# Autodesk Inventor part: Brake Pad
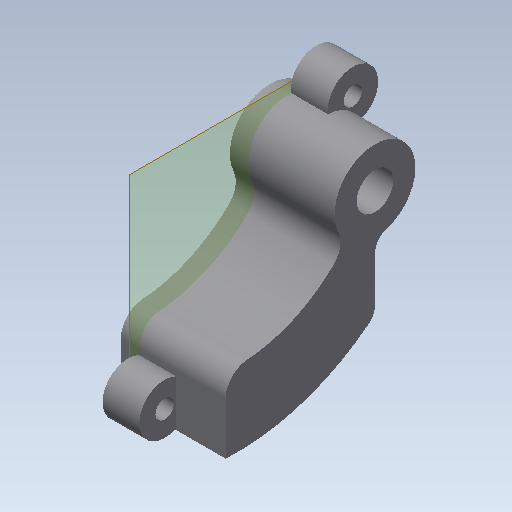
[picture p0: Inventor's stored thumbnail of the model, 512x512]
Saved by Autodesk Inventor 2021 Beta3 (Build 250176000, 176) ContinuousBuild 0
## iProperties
Created: 2012-08
Part Number: Brake Pad
Material: Generic
Document SubType Name: Modeling
Designer: John
Density: 1 g/cm^3
Appearance: Default
Author: John
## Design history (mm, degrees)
sketch "Sketch1"
  geometry: L1 (7.62, -5.283)-(7.62, -8.958); L2 (-0.635, -11.743)-(-0.635, -7.593); A1 r 11.76 centre (0, 0) between (-0.635, -11.743) and (7.62, -8.958); A2 r 7.62 centre (0, 0) between (-0.635, -7.593) and (6.047, -4.636); A3 r 2.235 centre (7.62, -3.048) between (7.62, -5.283) and (6.047, -4.636); 1 further point
  constraints: 6 point on circle, 4 end point, 3 centre point, 2 coincident, 1 parallel, 1 vertical, 1 vertical alignment
  dimensions: "d0" = 11.7602 radius of A1; "d1" = 7.62 radius of A2; "d8" = 2.2352 radius of A3; "d9" = 7.62 horizontal distance of A3.centre A2.centre; "d10" = 3.048 vertical distance of A1.centre A3.centre; "d11" = 0.635 distance from line of point (0, 0) L2
extrude "Extrusion1" new body sketch "Sketch1" distance "d12" = 5.7912; taper "d13" = 0 deg
fillet "Fillet1" dims "d14" = 1.27
fillet "Fillet2" dims "d15" = 0.889
fillet "Fillet3" dims "d16" = 0.889
workplane "Work Plane1"
sketch "Sketch2"
  geometry: L1 (-7.593, -0.635)-(-11.743, -0.635) reference; L2 (-8.537, 7.62)-(-6.043, 7.62) reference; C1 r 1.397 at (-10.414, -1.27); C2 r 1.397 at (-0.635, 9.144); A1 r 1.27 centre (-4.534, 4.446) between (-3.996, 5.596) and (-5.441, 5.335) reference; A2 r 7.62 centre (0, 0) between (-5.441, 5.335) and (-7.593, -0.635) reference; A3 r 11.76 centre (0, 0) between (-9.235, 7.281) and (-11.743, -0.635) reference; A4 r 0.889 centre (-8.537, 6.731) between (-8.537, 7.62) and (-9.235, 7.281) reference; A5 r 0.889 centre (-6.043, 8.509) between (-6.043, 7.62) and (-5.191, 8.256) reference; A6 r 2.235 centre (-3.048, 7.62) between (-3.996, 5.596) and (-5.191, 8.256) reference; 1 further point
  constraints: 2 centre point
  dimensions: "d18" = 1.397 radius of C1; "d19" = 1.27 vertical distance of point (0, 0) C1.centre; "d20" = 10.414 horizontal distance of point (0, 0) C1.centre; "d21" = 1.397 radius of C2; "d22" = 0.635 horizontal distance of point (0, 0) C2.centre; "d23" = 9.144 vertical distance of point (0, 0) C2.centre
extrude "Extrusion2" join sketch "Sketch2" distance "d24" = 2.032; taper "d25" = 0 deg
fillet "Fillet4" dims "d26" = 1.27
sketch "Sketch3"
  geometry: L1 (9.17, -0.635)-(11.658, -0.635) reference; A1 r 1.397 centre (0.635, 9.144) between (1.964, 9.575) and (0.817, 7.759) reference; A2 r 1.397 centre (10.414, -1.27) between (9.17, -0.635) and (11.658, -0.635) reference; 1 further point
hole "Hole1" sketch "Sketch3" at (10.414, -1.27), (0.635, 9.144) diameter "d28" = 1.016; stored, may be unused: countersink angle "d32" = 82 deg, drill point angle "d34" = 118 deg; dims "d29" = 19.05, "d30" = 9.525, "d31" = 6.35, "d33" = 25.4
sketch "Sketch4"
  geometry: A1 r 2.235 centre (3.048, 7.62) between (5.191, 8.256) and (3.996, 5.596) reference
hole "Hole2" sketch "Sketch4" at (3.048, 7.62) diameter "d35" = 2.032; stored, may be unused: countersink angle "d39" = 82 deg, drill point angle "d41" = 118 deg; dims "d36" = 19.05, "d37" = 9.525, "d38" = 6.35, "d40" = 25.4
body "Solid1"
node "Projected Loop1"
node "Project Cut Edges1"
other parameters: "d17" = -1.016
